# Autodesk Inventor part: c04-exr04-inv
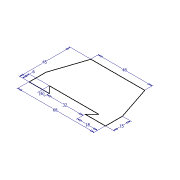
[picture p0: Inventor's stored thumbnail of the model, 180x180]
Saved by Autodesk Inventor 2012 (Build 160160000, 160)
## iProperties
Shininess: 64.0
Length Units: 11269
Angle Units: 11279
Time Units: 11290
Mass Units: 11283
Length Display Precision: 3
Angle Display Precision: 2
Compacted: True
Created: 2002-02
Part Number: c04-exr04-inv
Document SubType Name: Modeling
Density: 1 g/cm^3
Material: Default
Density: 0.0
Volumn: 0.0
Area: 0.0
PropertySet Name: Model Information
Control State: 0
Master: False
Checked Out: False
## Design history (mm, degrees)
sketch "Sketch1"
  geometry: L1 (-37.52, -4.549)-(-37.52, -19.549); L2 (-37.52, -19.549)-(-19.52, -19.549); L3 (-19.52, -19.549)-(-25.52, -13.549); L4 (-25.52, -13.549)-(18.48, -13.549); L5 (18.48, -13.549)-(12.48, -19.549); L6 (12.48, -19.549)-(30.48, -19.549); L7 (30.48, -19.549)-(30.48, -4.549); L8 (30.48, -4.549)-(20.48, 25.451); L9 (20.48, 25.451)-(-27.52, 25.451); L10 (-27.52, 25.451)-(-37.52, -4.549)
  constraints: 20 end point, 4 equal length, 2 parallel, 2 perpendicular, 1 collinear, 1 horizontal, 1 vertical
  dimensions: "d0" = 18 distance of L5.end L6.end; "d2" = 68 distance between parallel lines of L7 L1; "d3" = 6 horizontal distance of L2.end L3.end; "d4" = 45 distance between parallel lines of L9 L2; "d5" = 15 distance of L6.end L7.end; "d6" = 48 distance of L8.end L9.end; "d8" = 32 distance of L5.end L2.end; "d9" = 6 horizontal distance of L3.end L2.end (derived)
